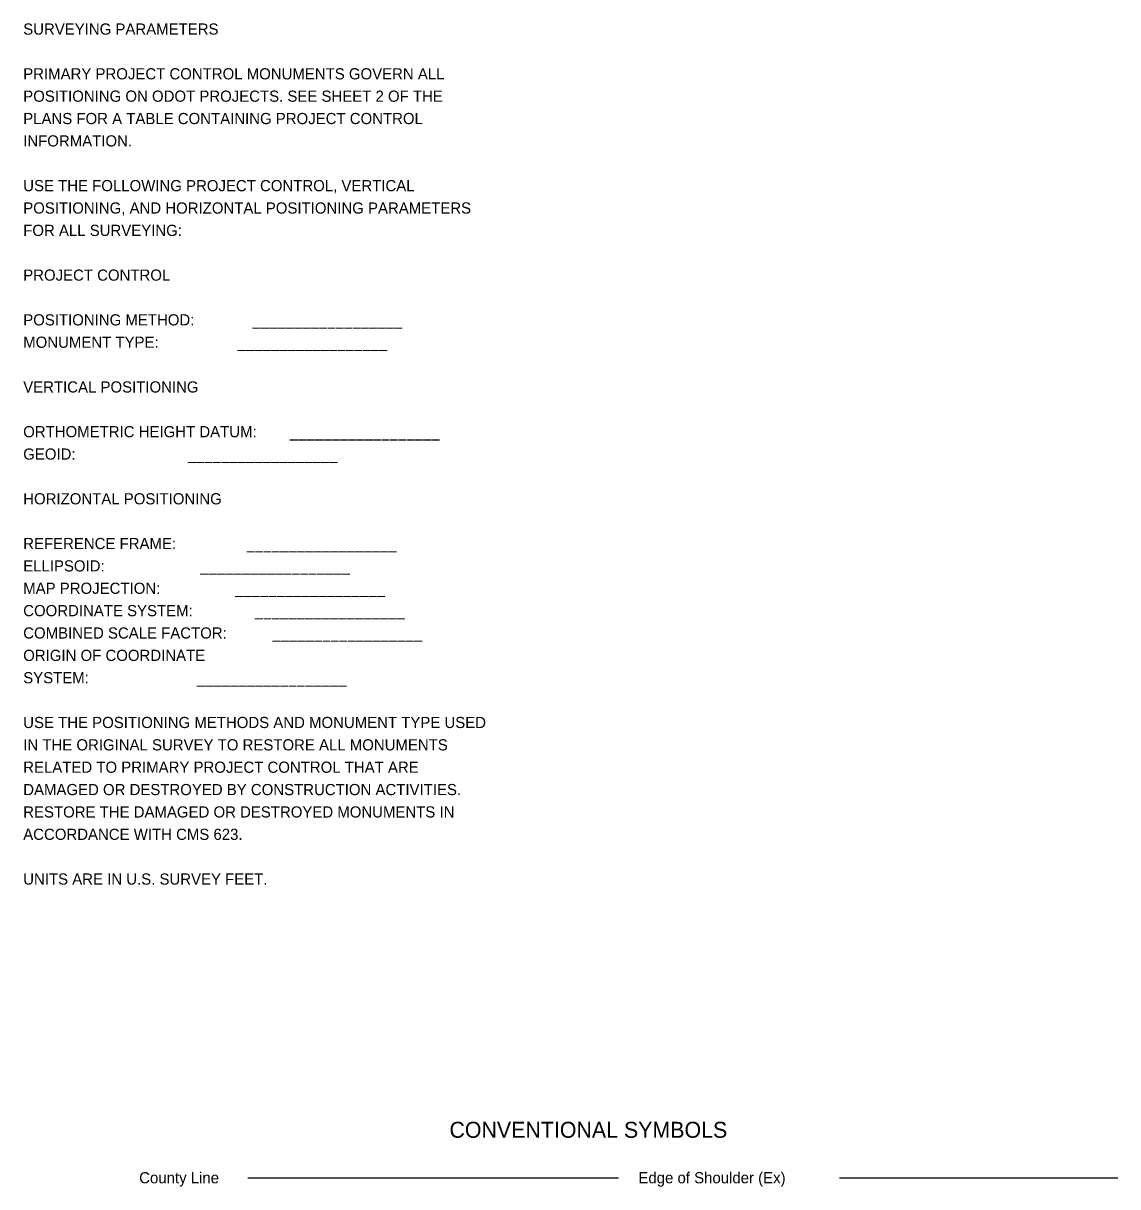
# Model space of a CAD drawing. Extents: x -9 to 100, y -25 to 48.
# Drawn here: x 39.91 to 53.61, y 5.37 to 19.94 of the extents above; entities that cross this region are included whole.
import ezdxf

# ---------------------------------------------------------------- set-up
doc = ezdxf.new("R2010")
doc.units = 0
doc.layers.add('SH_Text', color=7, linetype='Continuous')

msp = doc.modelspace()

# ---------------------------------------------------------------- linework, layer by layer
at = {"layer": 'SH_Text'}
for p, q in [((42.723, 5.485), (47.362, 5.485)), ((50.129, 5.485), (53.612, 5.485))]:
    msp.add_line(p, q, dxfattribs=at)

# ---------------------------------------------------------------- texts
for s, height, p in [('SURVEYING PARAMETERS', 0.14, (39.91, 19.794)), ('PRIMARY PROJECT CONTROL MONUMENTS GOVERN ALL', 0.14, (39.91, 19.234)), ('POSITIONING ON ODOT PROJECTS. SEE SHEET 2 OF THE', 0.14, (39.91, 18.954)), ('PLANS FOR A TABLE CONTAINING PROJECT CONTROL', 0.14, (39.91, 18.674)), ('INFORMATION.', 0.14, (39.91, 18.394)), ('USE THE FOLLOWING PROJECT CONTROL, VERTICAL', 0.14, (39.91, 17.834)), ('POSITIONING, AND HORIZONTAL POSITIONING PARAMETERS', 0.14, (39.91, 17.554)), ('FOR ALL SURVEYING:', 0.14, (39.91, 17.274)), ('PROJECT CONTROL', 0.14, (39.91, 16.714)), ('POSITIONING METHOD:              __________________', 0.14, (39.91, 16.154)), ('MONUMENT TYPE:                   __________________', 0.14, (39.91, 15.874)), ('VERTICAL POSITIONING', 0.14, (39.91, 15.314)), ('ORTHOMETRIC HEIGHT DATUM:        __________________', 0.14, (39.91, 14.754)), ('GEOID:                           __________________', 0.14, (39.91, 14.474)), ('HORIZONTAL POSITIONING', 0.14, (39.91, 13.914)), ('REFERENCE FRAME:                 __________________', 0.14, (39.91, 13.354)), ('ELLIPSOID:                       __________________', 0.14, (39.91, 13.074)), ('MAP PROJECTION:                  __________________', 0.14, (39.91, 12.794)), ('COORDINATE SYSTEM:               __________________', 0.14, (39.91, 12.514)), ('COMBINED SCALE FACTOR:           __________________', 0.14, (39.91, 12.234)), ('ORIGIN OF COORDINATE', 0.14, (39.91, 11.954)), ('SYSTEM:                          __________________', 0.14, (39.91, 11.674)), ('USE THE POSITIONING METHODS AND MONUMENT TYPE USED', 0.14, (39.91, 11.114)), ('IN THE ORIGINAL SURVEY TO RESTORE ALL MONUMENTS', 0.14, (39.91, 10.834)), ('RELATED TO PRIMARY PROJECT CONTROL THAT ARE', 0.14, (39.91, 10.554)), ('DAMAGED OR DESTROYED BY CONSTRUCTION ACTIVITIES.', 0.14, (39.91, 10.274)), ('RESTORE THE DAMAGED OR DESTROYED MONUMENTS IN', 0.14, (39.91, 9.994)), ('ACCORDANCE WITH CMS 623.', 0.14, (39.91, 9.714)), ('UNITS ARE IN U.S. SURVEY FEET.', 0.14, (39.91, 9.154)), ('CONVENTIONAL SYMBOLS', 0.2, (45.246, 5.985)), ('County Line', 0.14, (41.362, 5.415)), ('Edge of Shoulder (Ex)', 0.14, (47.612, 5.415))]:
    msp.add_text(s, height=height, dxfattribs=at).set_placement(p)

doc.saveas('drawing.dxf')
